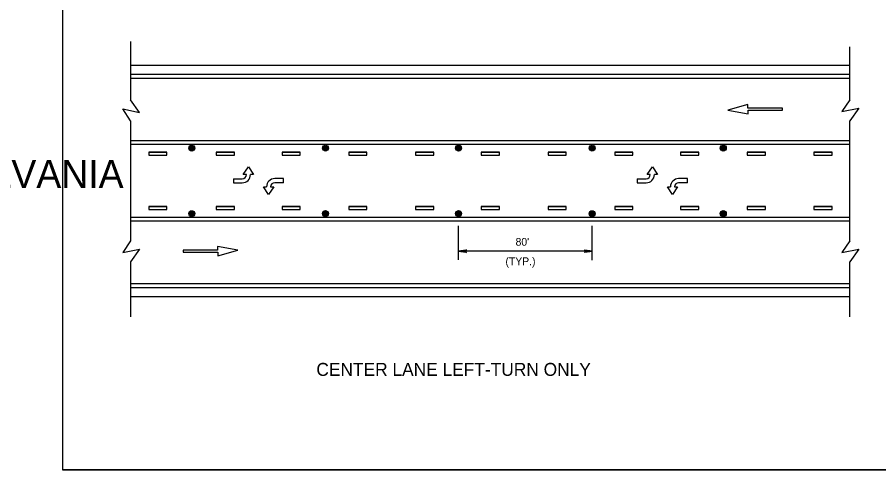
# Model space of a CAD drawing. Extents: x 639362 to 641108, y 298458 to 299646.
# Drawn here: x 640225.9 to 640558.2, y 299066.6 to 299241.2 of the extents above; entities that cross this region are included whole.
import ezdxf

# ---------------------------------------------------------------- set-up
doc = ezdxf.new("R2010")
doc.units = 0
for name, color, linetype in [('1', 7, 'Continuous'), ('2', 7, 'Continuous'), ('3', 7, 'Continuous')]:
    doc.layers.add(name, color=color, linetype=linetype)

# ---------------------------------------------------------------- blocks, each defined once
blk = doc.blocks.new('RARROW')
at = {"layer": '3'}
blk.add_lwpolyline([(-2.2695, 0.285), (-2.184875, 0.12075), (0, 0), (-2.2695, 0.285), (-2.38575, 0.384625), (0, 0), (-2.183125, -0.108), (-2.262875, -0.2705), (0, 0), (-2.38575, -0.379125), (-2.262875, -0.2705)], dxfattribs=at)

msp = doc.modelspace()

# ---------------------------------------------------------------- linework, layer by layer
at = {"layer": '1'}
for p, q in [((640243.31, 299630.63), (640243.31, 299066.63)), ((641029.31, 299066.63), (640243.31, 299066.63)), ((640243.31, 299066.63), (640829.31, 299066.63))]:
    msp.add_line(p, q, dxfattribs=at)
at = {"layer": '2'}
for p, q in [((640269.57, 299231.87), (640269.57, 299209.4)), ((640547.01, 299209.4), (640547.01, 299229.85)), ((640269.57, 299222.76), (640547.01, 299222.76)), ((640269.57, 299219.26), (640547.01, 299219.26)), ((640269.57, 299217.76), (640547.01, 299217.76)), ((640273.06, 299204.51), (640269.57, 299209.4)), ((640547.01, 299209.4), (640543.96, 299204.82)), ((640269.57, 299201.27), (640266.53, 299205.85)), ((640266.53, 299205.85), (640273.06, 299204.51)), ((640507.72, 299207.51), (640500, 299205.4)), ((640507.72, 299206.07), (640507.72, 299207.51)), ((640521.05, 299206.07), (640507.72, 299206.07)), ((640521.05, 299205.37), (640521.05, 299206.07)), ((640543.96, 299204.82), (640550.5, 299206.16)), ((640550.5, 299206.16), (640547.01, 299201.27)), ((640500, 299205.4), (640507.8, 299203.92)), ((640507.8, 299203.92), (640507.8, 299205.37)), ((640507.8, 299205.37), (640521.05, 299205.37)), ((640269.57, 299201.27), (640269.57, 299154.97)), ((640547.01, 299154.97), (640547.01, 299201.27)), ((640547.01, 299193.49), (640269.57, 299193.49)), ((640269.57, 299193.49), (640269.57, 299192.29)), ((640547.01, 299192.29), (640547.01, 299193.49)), ((640269.57, 299192.29), (640547.01, 299192.29)), ((640283.59, 299189.2), (640276.57, 299189.2)), ((640276.57, 299189.2), (640283.59, 299189.18)), ((640283.59, 299187.98), (640283.59, 299189.2)), ((640309.67, 299189.21), (640302.65, 299189.21)), ((640302.65, 299189.21), (640309.67, 299189.19)), ((640309.67, 299187.99), (640309.67, 299189.21)), ((640335.04, 299189.21), (640328.02, 299189.21)), ((640328.02, 299189.21), (640335.04, 299189.19)), ((640335.04, 299187.99), (640335.04, 299189.21)), ((640360.78, 299189.21), (640353.76, 299189.21)), ((640353.76, 299189.21), (640360.78, 299189.19)), ((640360.78, 299187.99), (640360.78, 299189.21)), ((640386.52, 299189.21), (640379.5, 299189.21)), ((640379.5, 299189.21), (640386.52, 299189.19)), ((640386.52, 299187.99), (640386.52, 299189.21)), ((640411.89, 299189.21), (640404.87, 299189.21)), ((640404.87, 299189.21), (640411.89, 299189.19)), ((640411.89, 299187.99), (640411.89, 299189.21)), ((640437.63, 299189.21), (640430.61, 299189.21)), ((640430.61, 299189.21), (640437.63, 299189.19)), ((640437.63, 299187.99), (640437.63, 299189.21)), ((640463.37, 299189.21), (640456.35, 299189.21)), ((640456.35, 299189.21), (640463.37, 299189.19)), ((640463.37, 299187.99), (640463.37, 299189.21)), ((640488.74, 299189.21), (640481.72, 299189.21)), ((640481.72, 299189.21), (640488.74, 299189.19)), ((640488.74, 299187.99), (640488.74, 299189.21)), ((640514.48, 299189.21), (640507.46, 299189.21)), ((640507.46, 299189.21), (640514.48, 299189.19)), ((640514.48, 299187.99), (640514.48, 299189.21)), ((640540.22, 299189.21), (640533.2, 299189.21)), ((640533.2, 299189.21), (640540.22, 299189.19)), ((640540.22, 299187.99), (640540.22, 299189.21)), ((640313.06, 299180.5), (640315.04, 299183.46)), ((640315.04, 299183.46), (640317.02, 299180.5)), ((640468.87, 299180.5), (640470.85, 299183.46)), ((640470.85, 299183.46), (640472.83, 299180.5)), ((640314.25, 299180.5), (640313.06, 299180.5)), ((640317.02, 299180.5), (640315.83, 299180.5)), ((640470.06, 299180.5), (640468.87, 299180.5)), ((640472.83, 299180.5), (640471.64, 299180.5)), ((640309.25, 299178.92), (640309.25, 299177.33)), ((640309.25, 299178.92), (640312.67, 299178.92)), ((640309.25, 299177.33), (640312.67, 299177.33)), ((640322.81, 299172.82), (640320.83, 299175.78)), ((640320.83, 299175.78), (640322.02, 299175.78)), ((640324.79, 299175.78), (640322.81, 299172.82)), ((640323.6, 299175.78), (640324.79, 299175.78)), ((640328.6, 299178.94), (640325.18, 299178.94)), ((640328.6, 299177.36), (640325.18, 299177.36)), ((640328.6, 299177.36), (640328.6, 299178.94)), ((640465.06, 299178.92), (640465.06, 299177.33)), ((640465.06, 299178.92), (640468.48, 299178.92)), ((640465.06, 299177.33), (640468.48, 299177.33)), ((640478.62, 299172.82), (640476.64, 299175.78)), ((640476.64, 299175.78), (640477.83, 299175.78)), ((640480.6, 299175.78), (640478.62, 299172.82)), ((640479.41, 299175.78), (640480.6, 299175.78)), ((640484.41, 299178.94), (640480.99, 299178.94)), ((640484.41, 299177.36), (640480.99, 299177.36)), ((640484.41, 299177.36), (640484.41, 299178.94)), ((640283.59, 299168.21), (640276.57, 299168.21)), ((640276.57, 299168.21), (640283.59, 299168.19)), ((640283.59, 299166.99), (640283.59, 299168.21)), ((640309.67, 299168.21), (640302.65, 299168.21)), ((640302.65, 299168.21), (640309.67, 299168.19)), ((640309.67, 299166.99), (640309.67, 299168.21)), ((640335.04, 299168.21), (640328.02, 299168.21)), ((640328.02, 299168.21), (640335.04, 299168.19)), ((640335.04, 299166.99), (640335.04, 299168.21)), ((640360.78, 299168.21), (640353.76, 299168.21)), ((640353.76, 299168.21), (640360.78, 299168.19)), ((640360.78, 299166.99), (640360.78, 299168.21)), ((640386.52, 299168.21), (640379.5, 299168.21)), ((640379.5, 299168.21), (640386.52, 299168.19)), ((640386.52, 299166.99), (640386.52, 299168.21)), ((640411.89, 299168.21), (640404.87, 299168.21)), ((640404.87, 299168.21), (640411.89, 299168.19)), ((640411.89, 299166.99), (640411.89, 299168.21)), ((640437.63, 299168.21), (640430.61, 299168.21)), ((640430.61, 299168.21), (640437.63, 299168.19)), ((640437.63, 299166.99), (640437.63, 299168.21)), ((640463.37, 299168.21), (640456.35, 299168.21)), ((640456.35, 299168.21), (640463.37, 299168.19)), ((640463.37, 299166.99), (640463.37, 299168.21)), ((640488.74, 299168.21), (640481.72, 299168.21)), ((640481.72, 299168.21), (640488.74, 299168.19)), ((640488.74, 299166.99), (640488.74, 299168.21)), ((640514.48, 299168.21), (640507.46, 299168.21)), ((640507.46, 299168.21), (640514.48, 299168.19)), ((640514.48, 299166.99), (640514.48, 299168.21)), ((640540.22, 299168.21), (640533.2, 299168.21)), ((640533.2, 299168.21), (640540.22, 299168.19)), ((640540.22, 299166.99), (640540.22, 299168.21)), ((640547.01, 299163.89), (640269.57, 299163.89)), ((640269.57, 299163.89), (640269.57, 299162.69)), ((640269.57, 299162.69), (640547.01, 299162.69)), ((640547.01, 299162.69), (640547.01, 299163.89)), ((640396.11, 299147.58), (640396.11, 299160.69)), ((640447.64, 299147.51), (640447.64, 299160.69)), ((640269.57, 299154.97), (640266.53, 299150.39)), ((640310.94, 299151.3), (640303.14, 299152.78)), ((640303.14, 299152.78), (640303.14, 299151.33)), ((640547.01, 299154.97), (640543.96, 299150.39)), ((640266.53, 299150.39), (640273.06, 299151.74)), ((640273.06, 299151.74), (640269.57, 299146.85)), ((640303.14, 299151.33), (640289.89, 299151.33)), ((640289.89, 299151.33), (640289.89, 299150.63)), ((640289.89, 299150.63), (640303.22, 299150.63)), ((640303.22, 299149.18), (640310.94, 299151.3)), ((640303.22, 299150.63), (640303.22, 299149.18)), ((640447.64, 299150.97), (640396.11, 299150.97)), ((640543.96, 299150.39), (640550.5, 299151.74)), ((640550.5, 299151.74), (640547.01, 299146.85)), ((640269.57, 299146.85), (640269.57, 299125.58)), ((640547.01, 299125.58), (640547.01, 299146.85)), ((640269.57, 299138.48), (640547.01, 299138.48)), ((640269.57, 299136.98), (640547.01, 299136.98)), ((640269.57, 299133.48), (640547.01, 299133.48))]:
    msp.add_line(p, q, dxfattribs=at)
for points in [[(640283.59, 299189.18), (640276.57, 299189.18), (640276.57, 299187.98), (640283.59, 299187.98)], [(640309.67, 299189.19), (640302.65, 299189.19), (640302.65, 299187.99), (640309.67, 299187.99)], [(640335.04, 299189.19), (640328.02, 299189.19), (640328.02, 299187.99), (640335.04, 299187.99)], [(640360.78, 299189.19), (640353.76, 299189.19), (640353.76, 299187.99), (640360.78, 299187.99)], [(640386.52, 299189.19), (640379.5, 299189.19), (640379.5, 299187.99), (640386.52, 299187.99)], [(640411.89, 299189.19), (640404.87, 299189.19), (640404.87, 299187.99), (640411.89, 299187.99)], [(640437.63, 299189.19), (640430.61, 299189.19), (640430.61, 299187.99), (640437.63, 299187.99)], [(640463.37, 299189.19), (640456.35, 299189.19), (640456.35, 299187.99), (640463.37, 299187.99)], [(640488.74, 299189.19), (640481.72, 299189.19), (640481.72, 299187.99), (640488.74, 299187.99)], [(640514.48, 299189.19), (640507.46, 299189.19), (640507.46, 299187.99), (640514.48, 299187.99)], [(640540.22, 299189.19), (640533.2, 299189.19), (640533.2, 299187.99), (640540.22, 299187.99)], [(640283.59, 299168.19), (640276.57, 299168.19), (640276.57, 299166.99), (640283.59, 299166.99)], [(640309.67, 299168.19), (640302.65, 299168.19), (640302.65, 299166.99), (640309.67, 299166.99)], [(640335.04, 299168.19), (640328.02, 299168.19), (640328.02, 299166.99), (640335.04, 299166.99)], [(640360.78, 299168.19), (640353.76, 299168.19), (640353.76, 299166.99), (640360.78, 299166.99)], [(640386.52, 299168.19), (640379.5, 299168.19), (640379.5, 299166.99), (640386.52, 299166.99)], [(640411.89, 299168.19), (640404.87, 299168.19), (640404.87, 299166.99), (640411.89, 299166.99)], [(640437.63, 299168.19), (640430.61, 299168.19), (640430.61, 299166.99), (640437.63, 299166.99)], [(640463.37, 299168.19), (640456.35, 299168.19), (640456.35, 299166.99), (640463.37, 299166.99)], [(640488.74, 299168.19), (640481.72, 299168.19), (640481.72, 299166.99), (640488.74, 299166.99)], [(640514.48, 299168.19), (640507.46, 299168.19), (640507.46, 299166.99), (640514.48, 299166.99)], [(640540.22, 299168.19), (640533.2, 299168.19), (640533.2, 299166.99), (640540.22, 299166.99)]]:
    msp.add_lwpolyline(points, dxfattribs=at)
for centre, radius in [((640293.18, 299190.72), 1.15), ((640293.18, 299190.72), 1.07), ((640293.18, 299190.72), 0.985), ((640293.18, 299190.72), 0.904), ((640293.18, 299190.72), 0.822), ((640293.18, 299190.72), 0.741), ((640293.18, 299190.72), 0.659), ((640293.18, 299190.72), 0.578), ((640293.18, 299190.72), 0.496), ((640293.18, 299190.72), 0.414), ((640293.18, 299190.72), 0.333), ((640293.18, 299190.72), 0.251), ((640293.18, 299190.72), 0.17), ((640293.18, 299190.72), 0.0881), ((640344.77, 299190.73), 1.15), ((640344.77, 299190.73), 1.07), ((640344.77, 299190.73), 0.985), ((640344.77, 299190.73), 0.904), ((640344.77, 299190.73), 0.822), ((640344.77, 299190.73), 0.741), ((640344.77, 299190.73), 0.659), ((640344.77, 299190.73), 0.578), ((640344.77, 299190.73), 0.496), ((640344.77, 299190.73), 0.414), ((640344.77, 299190.73), 0.333), ((640344.77, 299190.73), 0.251), ((640344.77, 299190.73), 0.17), ((640344.77, 299190.73), 0.0881), ((640396.11, 299190.75), 1.15), ((640396.11, 299190.75), 1.07), ((640396.11, 299190.75), 0.985), ((640396.11, 299190.75), 0.904), ((640396.11, 299190.75), 0.822), ((640396.11, 299190.75), 0.741), ((640396.11, 299190.75), 0.659), ((640396.11, 299190.75), 0.578), ((640396.11, 299190.75), 0.496), ((640396.11, 299190.75), 0.414), ((640396.11, 299190.75), 0.333), ((640396.11, 299190.75), 0.251), ((640396.11, 299190.75), 0.17), ((640396.11, 299190.75), 0.0881), ((640447.64, 299190.73), 1.15), ((640447.64, 299190.73), 1.07), ((640447.64, 299190.73), 0.985), ((640447.64, 299190.73), 0.904), ((640447.64, 299190.73), 0.822), ((640447.64, 299190.73), 0.741), ((640447.64, 299190.73), 0.659), ((640447.64, 299190.73), 0.578), ((640447.64, 299190.73), 0.496), ((640447.64, 299190.73), 0.414), ((640447.64, 299190.73), 0.333), ((640447.64, 299190.73), 0.251), ((640447.64, 299190.73), 0.17), ((640447.64, 299190.73), 0.0881), ((640498.21, 299190.73), 1.15), ((640498.21, 299190.73), 1.07), ((640498.21, 299190.73), 0.985), ((640498.21, 299190.73), 0.904), ((640498.21, 299190.73), 0.822), ((640498.21, 299190.73), 0.741), ((640498.21, 299190.73), 0.659), ((640498.21, 299190.73), 0.578), ((640498.21, 299190.73), 0.496), ((640498.21, 299190.73), 0.414), ((640498.21, 299190.73), 0.333), ((640498.21, 299190.73), 0.251), ((640498.21, 299190.73), 0.17), ((640498.21, 299190.73), 0.0881), ((640293.18, 299165.43), 1.15), ((640293.18, 299165.43), 1.07), ((640293.18, 299165.43), 0.985), ((640293.18, 299165.43), 0.904), ((640293.18, 299165.43), 0.822), ((640293.18, 299165.43), 0.741), ((640293.18, 299165.43), 0.659), ((640293.18, 299165.43), 0.578), ((640293.18, 299165.43), 0.496), ((640293.18, 299165.43), 0.414), ((640344.76, 299165.45), 1.15), ((640344.76, 299165.45), 1.07), ((640344.76, 299165.45), 0.985), ((640344.76, 299165.45), 0.904), ((640344.76, 299165.45), 0.822), ((640344.76, 299165.45), 0.741), ((640344.76, 299165.45), 0.659), ((640344.76, 299165.45), 0.578), ((640344.76, 299165.45), 0.496), ((640344.76, 299165.45), 0.414), ((640396.11, 299165.44), 1.15), ((640396.11, 299165.44), 1.07), ((640396.11, 299165.44), 0.985), ((640396.11, 299165.44), 0.904), ((640396.11, 299165.44), 0.822), ((640396.11, 299165.44), 0.741), ((640396.11, 299165.44), 0.659), ((640396.11, 299165.44), 0.578), ((640396.11, 299165.44), 0.496), ((640396.11, 299165.44), 0.414), ((640447.63, 299165.42), 1.15), ((640447.63, 299165.42), 1.07), ((640447.63, 299165.42), 0.985), ((640447.63, 299165.42), 0.904), ((640447.63, 299165.42), 0.822), ((640447.63, 299165.42), 0.741), ((640447.63, 299165.42), 0.659), ((640447.63, 299165.42), 0.578), ((640447.63, 299165.42), 0.496), ((640447.63, 299165.42), 0.414), ((640498.21, 299165.44), 1.15), ((640498.21, 299165.44), 1.07), ((640498.21, 299165.44), 0.985), ((640498.21, 299165.44), 0.904), ((640498.21, 299165.44), 0.822), ((640498.21, 299165.44), 0.741), ((640498.21, 299165.44), 0.659), ((640498.21, 299165.44), 0.578), ((640498.21, 299165.44), 0.496), ((640498.21, 299165.44), 0.414), ((640293.18, 299165.43), 0.333), ((640293.18, 299165.43), 0.251), ((640293.18, 299165.43), 0.17), ((640293.18, 299165.43), 0.0881), ((640344.76, 299165.45), 0.333), ((640344.76, 299165.45), 0.251), ((640344.76, 299165.45), 0.17), ((640344.76, 299165.45), 0.0881), ((640396.11, 299165.44), 0.333), ((640396.11, 299165.44), 0.251), ((640396.11, 299165.44), 0.17), ((640396.11, 299165.44), 0.0881), ((640447.63, 299165.42), 0.333), ((640447.63, 299165.42), 0.251), ((640447.63, 299165.42), 0.17), ((640447.63, 299165.42), 0.0881), ((640498.21, 299165.44), 0.333), ((640498.21, 299165.44), 0.251), ((640498.21, 299165.44), 0.17), ((640498.21, 299165.44), 0.0881)]:
    msp.add_circle(centre, radius, dxfattribs=at)
for centre, radius, start, end in [((640312.67, 299180.5), 1.58, 270, 0), ((640312.67, 299180.5), 3.16, 270, 0), ((640468.48, 299180.5), 1.58, 270, 0), ((640468.48, 299180.5), 3.16, 270, 0), ((640325.18, 299175.78), 3.16, 90, 180), ((640325.18, 299175.78), 1.58, 90, 180), ((640480.99, 299175.78), 3.16, 90, 180), ((640480.99, 299175.78), 1.58, 90, 180)]:
    msp.add_arc(centre, radius, start, end, dxfattribs=at)

# ---------------------------------------------------------------- block references
at = {"layer": '2', "xscale": 1.2574347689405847, "yscale": 1.3092961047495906, "rotation": 180}
msp.add_blockref('RARROW', (640396.11, 299150.97), dxfattribs=at)
at = {"layer": '2', "xscale": 1.2574347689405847, "yscale": 1.3092961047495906}
msp.add_blockref('RARROW', (640447.64, 299150.97), dxfattribs=at)

# ---------------------------------------------------------------- texts
at = {"layer": '1'}
msp.add_text('COMMONWEALTH OF PENNSYLVANIA', height=10.7828, dxfattribs=at).set_placement((640000.9, 299175.36))
at = {"layer": '2'}
for s, height, p in [("80'", 3, (640418.09, 299153.06)), ('(TYP.)', 3, (640414.19, 299145.56)), ('CENTER LANE LEFT-TURN ONLY', 5, (640341.25, 299102.85))]:
    msp.add_text(s, height=height, dxfattribs=at).set_placement(p)

doc.saveas('drawing.dxf')
